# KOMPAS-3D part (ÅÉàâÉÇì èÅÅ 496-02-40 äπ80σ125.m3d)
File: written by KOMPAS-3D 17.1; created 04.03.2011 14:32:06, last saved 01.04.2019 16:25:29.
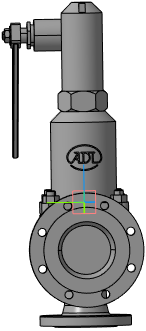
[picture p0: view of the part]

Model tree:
1. Операция без истории:1

Referenced files in C:\Users\tra\Desktop\Детали с марк. для Сферы\bsv\Desktop\Si 57\: VIC_496_80x125_3d.a3d
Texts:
  Viktor2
